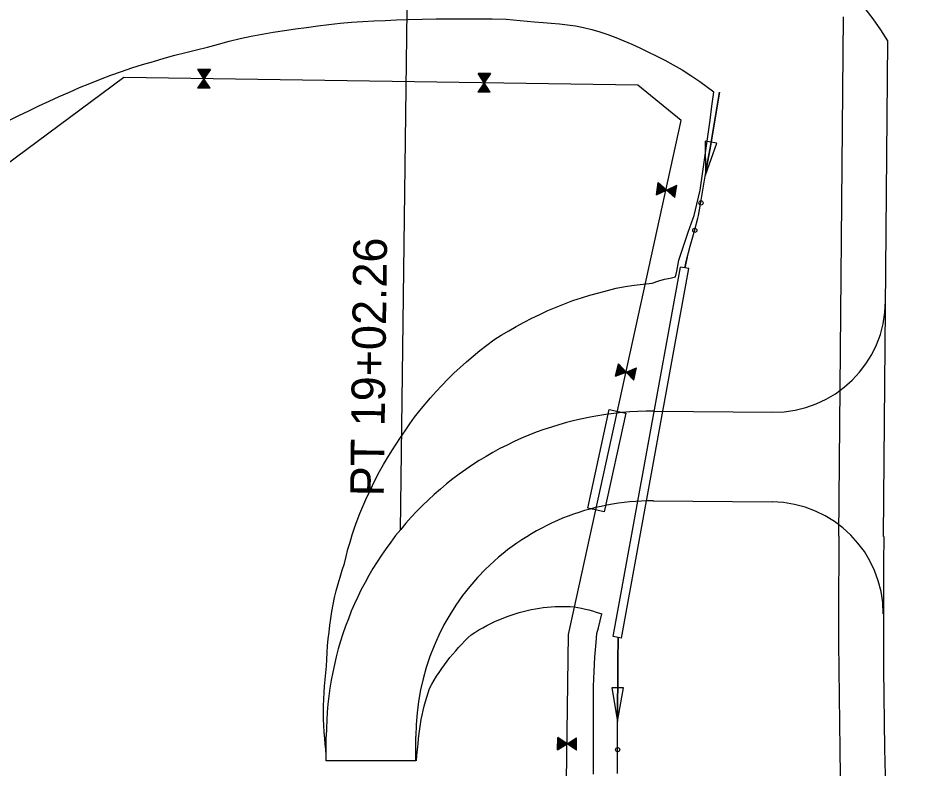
# Model space of a CAD drawing. Extents: x 1311167 to 1314552, y 2087587 to 2090602.
# Drawn here: x 1313838.8 to 1313997.5, y 2090039.3 to 2090173.1 of the extents above; entities that cross this region are included whole.
import ezdxf

# ---------------------------------------------------------------- set-up
doc = ezdxf.new("R2010")
doc.units = 0
for name, color, linetype in [('MOT_Shoulder_1A', 7, 'Continuous'), ('R_Horz Alg Stationing', 7, 'Continuous'), ('R_Proposed Road', 7, 'Continuous'), ('R_Shld_GR', 7, 'Continuous'), ('S_DITCHLINE', 7, 'Continuous'), ('S_DROP_INLET', 7, 'Continuous'), ('S_EDGE_BITUMINOUS', 7, 'Continuous'), ('S_EDGE_CONCRETE', 7, 'Continuous'), ('S_EDGE_PAVEMENT', 7, 'Continuous'), ('S_PAVEMENT_CROWN', 7, 'Continuous')]:
    doc.layers.add(name, color=color, linetype=linetype)

msp = doc.modelspace()

# ---------------------------------------------------------------- linework, layer by layer
at = {"layer": 'MOT_Shoulder_1A'}
for p, q in [((1313952.36, 2090102.93), (1313973.52, 2090102.75)), ((1313952.22, 2090086.93), (1313973.45, 2090086.75)), ((1313893.86, 2090040.57), (1313893.86, 2090044.93)), ((1313909.86, 2090040.57), (1313909.86, 2090044.93)), ((1313909.86, 2090040.57), (1313893.86, 2090040.57))]:
    msp.add_line(p, q, dxfattribs=at)
for centre, radius, start, end in [((1313973.69, 2090122.75), 20, 269.5, 359.5), ((1313951.86, 2090044.93), 58, 89.5, 180), ((1313951.86, 2090044.93), 42, 89.5, 180), ((1313973.27, 2090066.75), 20, 0.048, 89.5)]:
    msp.add_arc(centre, radius, start, end, dxfattribs=at)
at = {"layer": 'R_Horz Alg Stationing'}
msp.add_arc((1313903.45, 2090013.7), 190.97, 89.1292, 178.95, dxfattribs=at)
at = {"layer": 'R_Proposed Road'}
msp.add_arc((1313906.1, 2090010.65), 201.04, 89.25, 178.95, dxfattribs=at)
msp.add_arc((1313906.1, 2090010.65), 201.04, 89.25, 178.95, dxfattribs=at)
at = {"layer": 'R_Shld_GR'}
msp.add_lwpolyline([(1313908.73, 2090211.67), (1313907.03, 2090081.68)], dxfattribs=at)
at = {"layer": 'S_DITCHLINE'}
for p, q in [((1313963.58, 2090150.78), (1313961.49, 2090151.13)), ((1313961.49, 2090151.13), (1313961.53, 2090145.04)), ((1313961.53, 2090145.04), (1313963.58, 2090150.78)), ((1313946.92, 2090053.57), (1313944.81, 2090053.58)), ((1313944.81, 2090053.58), (1313945.84, 2090047.58)), ((1313946.92, 2090053.57), (1313944.81, 2090053.58)), ((1313944.81, 2090053.58), (1313945.84, 2090047.58)), ((1313945.84, 2090047.58), (1313946.92, 2090053.57)), ((1313945.84, 2090047.58), (1313946.92, 2090053.57))]:
    msp.add_line(p, q, dxfattribs=at)
for points in [[(1313957.84, 2090128.51), (1313958.13, 2090129.88), (1313958.81, 2090132.38), (1313959.49, 2090134.87), (1313960.17, 2090137.37), (1313960.31, 2090137.86), (1313960.65, 2090139.86), (1313961.08, 2090142.36), (1313961.5, 2090144.85), (1313961.92, 2090147.35), (1313962.35, 2090149.85), (1313962.77, 2090152.34), (1313963.19, 2090154.84), (1313963.6, 2090157.34), (1313964.02, 2090159.83)], [(1313964.02, 2090159.83), (1313963.6, 2090157.34), (1313963.19, 2090154.84), (1313962.77, 2090152.34), (1313962.35, 2090149.85), (1313961.92, 2090147.35), (1313961.53, 2090145.04)], [(1313958.26, 2090130.38), (1313958.13, 2090129.88), (1313957.84, 2090128.51)], [(1313958.27, 2090130.42), (1313958.26, 2090130.38)], [(1313945.82, 2090038.28), (1313945.82, 2090040.89), (1313945.83, 2090043.49), (1313945.83, 2090046.1), (1313945.84, 2090048.7), (1313945.85, 2090051.3), (1313945.87, 2090053.91), (1313945.89, 2090056.51), (1313945.91, 2090059.12), (1313945.93, 2090061.72), (1313945.94, 2090062.58)], [(1313945.94, 2090062.58), (1313945.93, 2090061.72), (1313945.91, 2090059.12), (1313945.89, 2090056.51), (1313945.87, 2090053.91), (1313945.85, 2090051.3), (1313945.84, 2090048.7), (1313945.84, 2090047.58)], [(1313945.94, 2090062.58), (1313945.93, 2090061.72), (1313945.91, 2090059.12), (1313945.89, 2090056.51), (1313945.87, 2090053.91), (1313945.85, 2090051.3), (1313945.84, 2090048.7), (1313945.84, 2090047.58)]]:
    msp.add_lwpolyline(points, dxfattribs=at)
for centre in [(1313960.73, 2090140.1), (1313959.62, 2090135.21), (1313945.86, 2090042.57), (1313945.86, 2090042.57)]:
    msp.add_circle(centre, 0.375, dxfattribs=at)
at = {"layer": 'S_DROP_INLET'}
for p, q in [((1313872.03, 2090162.25), (1313870.94, 2090163.94)), ((1313872.05, 2090162.29), (1313870.99, 2090163.94)), ((1313872.11, 2090162.41), (1313871.12, 2090163.93)), ((1313872.19, 2090162.49), (1313871.26, 2090163.93)), ((1313872.25, 2090162.6), (1313871.39, 2090163.93)), ((1313872.32, 2090162.69), (1313871.52, 2090163.93)), ((1313872.38, 2090162.81), (1313871.66, 2090163.93)), ((1313872.46, 2090162.89), (1313871.79, 2090163.92)), ((1313872.51, 2090163.01), (1313871.92, 2090163.92)), ((1313873.17, 2090163.9), (1313872.03, 2090162.25)), ((1313872.59, 2090163.1), (1313872.06, 2090163.92)), ((1313872.64, 2090163.22), (1313872.23, 2090163.86)), ((1313872.73, 2090163.29), (1313872.32, 2090163.92)), ((1313872.8, 2090163.38), (1313872.46, 2090163.91)), ((1313872.87, 2090163.48), (1313872.59, 2090163.91)), ((1313872.93, 2090163.59), (1313872.72, 2090163.91)), ((1313873, 2090163.68), (1313872.86, 2090163.91)), ((1313873.07, 2090163.79), (1313872.99, 2090163.91)), ((1313873.14, 2090163.88), (1313873.13, 2090163.9)), ((1313872.03, 2090162.25), (1313870.9, 2090160.6)), ((1313872.05, 2090162.21), (1313870.94, 2090160.6)), ((1313872.1, 2090162.09), (1313871.07, 2090160.6)), ((1313873.12, 2090160.57), (1313872.03, 2090162.25)), ((1313922.03, 2090161.53), (1313920.94, 2090163.21)), ((1313922.04, 2090161.57), (1313920.98, 2090163.21)), ((1313922.1, 2090161.68), (1313921.12, 2090163.21)), ((1313922.18, 2090161.77), (1313921.25, 2090163.2)), ((1313922.24, 2090161.87), (1313921.38, 2090163.2)), ((1313922.32, 2090161.96), (1313921.52, 2090163.2)), ((1313922.37, 2090162.08), (1313921.65, 2090163.2)), ((1313922.45, 2090162.16), (1313921.78, 2090163.2)), ((1313922.51, 2090162.28), (1313921.92, 2090163.19)), ((1313923.16, 2090163.18), (1313922.03, 2090161.53)), ((1313922.58, 2090162.37), (1313922.05, 2090163.19)), ((1313922.64, 2090162.49), (1313922.23, 2090163.13)), ((1313922.73, 2090162.56), (1313922.32, 2090163.19)), ((1313922.8, 2090162.65), (1313922.45, 2090163.19)), ((1313922.86, 2090162.76), (1313922.59, 2090163.18)), ((1313922.93, 2090162.86), (1313922.72, 2090163.18)), ((1313923, 2090162.95), (1313922.85, 2090163.18)), ((1313923.06, 2090163.06), (1313922.99, 2090163.18)), ((1313923.14, 2090163.15), (1313923.12, 2090163.18)), ((1313872.18, 2090162.01), (1313871.21, 2090160.6)), ((1313872.24, 2090161.9), (1313871.34, 2090160.6)), ((1313872.31, 2090161.81), (1313871.47, 2090160.59)), ((1313872.36, 2090161.69), (1313871.61, 2090160.59)), ((1313872.44, 2090161.61), (1313871.74, 2090160.59)), ((1313872.49, 2090161.49), (1313871.87, 2090160.59)), ((1313872.56, 2090161.39), (1313872.01, 2090160.59)), ((1313872.61, 2090161.27), (1313872.18, 2090160.65)), ((1313872.7, 2090161.2), (1313872.28, 2090160.58)), ((1313872.77, 2090161.11), (1313872.41, 2090160.58)), ((1313872.83, 2090161), (1313872.54, 2090160.58)), ((1313872.89, 2090160.89), (1313872.68, 2090160.58)), ((1313872.96, 2090160.8), (1313872.81, 2090160.58)), ((1313873.02, 2090160.69), (1313872.94, 2090160.57)), ((1313873.09, 2090160.6), (1313873.08, 2090160.57)), ((1313922.03, 2090161.53), (1313920.89, 2090159.88)), ((1313922.04, 2090161.48), (1313920.94, 2090159.88)), ((1313922.1, 2090161.37), (1313921.07, 2090159.87)), ((1313922.17, 2090161.28), (1313921.2, 2090159.87)), ((1313922.23, 2090161.17), (1313921.34, 2090159.87)), ((1313922.3, 2090161.08), (1313921.47, 2090159.87)), ((1313922.36, 2090160.96), (1313921.6, 2090159.87)), ((1313922.43, 2090160.88), (1313921.74, 2090159.86)), ((1313922.49, 2090160.76), (1313921.87, 2090159.86)), ((1313922.56, 2090160.67), (1313922, 2090159.86)), ((1313923.11, 2090159.84), (1313922.03, 2090161.53)), ((1313922.61, 2090160.54), (1313922.18, 2090159.92)), ((1313957.22, 2090154.8), (1313949.47, 2090161.13)), ((1313922.7, 2090160.47), (1313922.27, 2090159.86)), ((1313922.77, 2090160.38), (1313922.4, 2090159.85)), ((1313922.83, 2090160.27), (1313922.54, 2090159.85)), ((1313922.89, 2090160.16), (1313922.67, 2090159.85)), ((1313922.96, 2090160.07), (1313922.8, 2090159.85)), ((1313923.02, 2090159.96), (1313922.94, 2090159.85)), ((1313923.09, 2090159.87), (1313923.07, 2090159.84)), ((1313954.12, 2090142.18), (1313953.03, 2090143.17)), ((1313954.22, 2090142.23), (1313953.05, 2090143.3)), ((1313954.33, 2090142.28), (1313953.07, 2090143.43)), ((1313954.43, 2090142.34), (1313953.09, 2090143.56)), ((1313954.6, 2090142.39), (1313953.11, 2090143.74)), ((1313954.55, 2090142.38), (1313953.11, 2090143.69)), ((1313954.6, 2090142.39), (1313956.41, 2090143.24)), ((1313954.63, 2090142.37), (1313956.4, 2090143.2)), ((1313954.74, 2090142.3), (1313956.38, 2090143.07)), ((1313952.78, 2090141.54), (1313954.6, 2090142.39)), ((1313952.81, 2090141.56), (1313952.79, 2090141.58)), ((1313952.91, 2090141.62), (1313952.81, 2090141.71)), ((1313953.03, 2090141.66), (1313952.83, 2090141.85)), ((1313953.13, 2090141.72), (1313952.85, 2090141.98)), ((1313953.25, 2090141.77), (1313952.87, 2090142.11)), ((1313953.36, 2090141.81), (1313952.89, 2090142.24)), ((1313953.46, 2090141.87), (1313952.91, 2090142.37)), ((1313953.67, 2090141.98), (1313952.95, 2090142.64)), ((1313953.77, 2090142.04), (1313952.97, 2090142.77)), ((1313953.54, 2090141.95), (1313952.98, 2090142.46)), ((1313953.9, 2090142.07), (1313952.99, 2090142.9)), ((1313953.99, 2090142.14), (1313953.01, 2090143.03)), ((1313956.08, 2090141.05), (1313954.6, 2090142.39)), ((1313954.81, 2090142.21), (1313956.36, 2090142.94)), ((1313954.91, 2090142.13), (1313956.34, 2090142.8)), ((1313954.99, 2090142.05), (1313956.32, 2090142.67)), ((1313955.1, 2090141.97), (1313956.3, 2090142.54)), ((1313955.17, 2090141.88), (1313956.28, 2090142.41)), ((1313955.28, 2090141.81), (1313956.26, 2090142.28)), ((1313955.36, 2090141.73), (1313956.24, 2090142.14)), ((1313955.47, 2090141.66), (1313956.16, 2090141.98)), ((1313955.52, 2090141.56), (1313956.2, 2090141.88)), ((1313955.61, 2090141.48), (1313956.18, 2090141.75)), ((1313955.7, 2090141.4), (1313956.16, 2090141.61)), ((1313955.8, 2090141.32), (1313956.14, 2090141.48)), ((1313955.88, 2090141.24), (1313956.12, 2090141.35)), ((1313955.98, 2090141.16), (1313956.1, 2090141.22)), ((1313956.06, 2090141.07), (1313956.08, 2090141.09)), ((1313947.33, 2090109.93), (1313945.97, 2090111.33)), ((1313947.37, 2090109.93), (1313945.98, 2090111.38)), ((1313945.5, 2090109.21), (1313947.37, 2090109.93)), ((1313945.98, 2090109.4), (1313945.63, 2090109.77)), ((1313946.1, 2090109.44), (1313945.66, 2090109.9)), ((1313946.21, 2090109.49), (1313945.69, 2090110.03)), ((1313946.42, 2090109.58), (1313945.74, 2090110.29)), ((1313946.29, 2090109.56), (1313945.76, 2090110.11)), ((1313946.53, 2090109.64), (1313945.77, 2090110.42)), ((1313946.65, 2090109.66), (1313945.8, 2090110.55)), ((1313946.75, 2090109.72), (1313945.83, 2090110.68)), ((1313946.88, 2090109.75), (1313945.86, 2090110.81)), ((1313946.98, 2090109.8), (1313945.89, 2090110.94)), ((1313947.1, 2090109.84), (1313945.91, 2090111.07)), ((1313947.2, 2090109.9), (1313945.94, 2090111.2)), ((1313947.37, 2090109.93), (1313949.24, 2090110.66)), ((1313948.76, 2090108.49), (1313947.37, 2090109.93)), ((1313947.41, 2090109.91), (1313949.23, 2090110.62)), ((1313947.51, 2090109.83), (1313949.2, 2090110.49)), ((1313947.57, 2090109.74), (1313949.17, 2090110.36)), ((1313947.67, 2090109.65), (1313949.14, 2090110.23)), ((1313947.74, 2090109.56), (1313949.11, 2090110.1)), ((1313947.84, 2090109.48), (1313949.08, 2090109.97)), ((1313947.91, 2090109.39), (1313949.06, 2090109.84)), ((1313948.01, 2090109.31), (1313949.03, 2090109.71)), ((1313945.53, 2090109.23), (1313945.51, 2090109.25)), ((1313945.64, 2090109.28), (1313945.54, 2090109.38)), ((1313945.76, 2090109.31), (1313945.57, 2090109.51)), ((1313945.86, 2090109.36), (1313945.6, 2090109.64)), ((1313948.09, 2090109.22), (1313949, 2090109.58)), ((1313948.19, 2090109.14), (1313948.9, 2090109.42)), ((1313948.24, 2090109.04), (1313948.94, 2090109.31)), ((1313948.32, 2090108.95), (1313948.91, 2090109.18)), ((1313948.41, 2090108.87), (1313948.88, 2090109.05)), ((1313948.5, 2090108.79), (1313948.86, 2090108.92)), ((1313948.58, 2090108.69), (1313948.83, 2090108.79)), ((1313948.67, 2090108.61), (1313948.8, 2090108.66)), ((1313948.74, 2090108.52), (1313948.77, 2090108.53)), ((1313936.8, 2090043.6), (1313935.18, 2090044.7)), ((1313936.84, 2090043.61), (1313935.19, 2090044.75)), ((1313936.84, 2090043.61), (1313938.52, 2090044.7)), ((1313936.88, 2090043.59), (1313938.52, 2090044.66)), ((1313935.15, 2090042.52), (1313936.84, 2090043.61)), ((1313935.69, 2090042.87), (1313935.16, 2090043.23)), ((1313935.58, 2090042.81), (1313935.16, 2090043.1)), ((1313936.19, 2090043.2), (1313935.17, 2090043.9)), ((1313936.07, 2090043.15), (1313935.17, 2090043.77)), ((1313935.98, 2090043.08), (1313935.17, 2090043.63)), ((1313935.79, 2090042.94), (1313935.17, 2090043.37)), ((1313936.68, 2090043.54), (1313935.18, 2090044.57)), ((1313936.59, 2090043.46), (1313935.18, 2090044.43)), ((1313936.48, 2090043.4), (1313935.18, 2090044.3)), ((1313936.39, 2090043.33), (1313935.18, 2090044.17)), ((1313936.27, 2090043.28), (1313935.18, 2090044.03)), ((1313935.86, 2090043.03), (1313935.23, 2090043.46)), ((1313938.49, 2090042.48), (1313936.84, 2090043.61)), ((1313936.99, 2090043.54), (1313938.52, 2090044.52)), ((1313937.08, 2090043.46), (1313938.51, 2090044.39)), ((1313937.18, 2090043.39), (1313938.51, 2090044.25)), ((1313937.27, 2090043.32), (1313938.51, 2090044.12)), ((1313937.39, 2090043.27), (1313938.51, 2090043.99)), ((1313937.47, 2090043.19), (1313938.51, 2090043.85)), ((1313937.59, 2090043.13), (1313938.51, 2090043.72)), ((1313937.68, 2090043.06), (1313938.5, 2090043.59)), ((1313937.8, 2090043), (1313938.44, 2090043.41)), ((1313937.87, 2090042.91), (1313938.5, 2090043.32)), ((1313937.96, 2090042.84), (1313938.5, 2090043.19)), ((1313938.07, 2090042.78), (1313938.5, 2090043.05)), ((1313935.47, 2090042.75), (1313935.16, 2090042.97)), ((1313935.38, 2090042.68), (1313935.16, 2090042.83)), ((1313935.27, 2090042.62), (1313935.16, 2090042.7)), ((1313935.18, 2090042.55), (1313935.16, 2090042.56)), ((1313938.17, 2090042.71), (1313938.49, 2090042.92)), ((1313938.27, 2090042.64), (1313938.49, 2090042.79)), ((1313938.37, 2090042.58), (1313938.49, 2090042.65)), ((1313938.46, 2090042.5), (1313938.49, 2090042.52))]:
    msp.add_line(p, q, dxfattribs=at)
for points in [[(1313873.17, 2090163.9), (1313870.94, 2090163.94)], [(1313949.47, 2090161.13), (1313857.75, 2090162.46), (1313774.8, 2090101), (1313754.78, 2090060.06), (1313753.38, 2090042.36)], [(1313923.16, 2090163.18), (1313920.94, 2090163.21)], [(1313873.12, 2090160.57), (1313870.9, 2090160.6)], [(1313949.47, 2090161.13), (1313949.47, 2090161.13)], [(1313923.11, 2090159.84), (1313920.89, 2090159.88)], [(1313938.24, 2089808.01), (1313935.42, 2089941.12), (1313937.11, 2090063.1), (1313957.22, 2090154.8)], [(1313952.78, 2090141.54), (1313953.11, 2090143.74)], [(1313956.08, 2090141.05), (1313956.41, 2090143.24)], [(1313945.5, 2090109.21), (1313945.98, 2090111.38)], [(1313948.76, 2090108.49), (1313949.24, 2090110.66)], [(1313935.15, 2090042.52), (1313935.19, 2090044.75)], [(1313938.49, 2090042.48), (1313938.52, 2090044.7)]]:
    msp.add_lwpolyline(points, dxfattribs=at)
msp.add_lwpolyline([(1313940.52, 2090085.66), (1313944.37, 2090103.24), (1313947.3, 2090102.6), (1313943.45, 2090085.01)], close=True, dxfattribs=at)
at = {"layer": 'S_EDGE_BITUMINOUS'}
for p, q in [((1313945.06, 2090062.74), (1313957.1, 2090128.65)), ((1313946.53, 2090062.47), (1313958.57, 2090128.38)), ((1313958.57, 2090128.38), (1313957.1, 2090128.65)), ((1313946.53, 2090062.47), (1313945.06, 2090062.74))]:
    msp.add_line(p, q, dxfattribs=at)
at = {"layer": 'S_EDGE_CONCRETE'}
for points in [[(1313837.21, 2090154.8), (1313838.99, 2090155.67), (1313840.78, 2090156.55), (1313842.57, 2090157.41), (1313844.37, 2090158.25), (1313846.19, 2090159.08), (1313848.01, 2090159.88), (1313849.84, 2090160.67), (1313851.68, 2090161.43), (1313853.53, 2090162.18), (1313855.39, 2090162.9), (1313857.28, 2090163.57), (1313859.17, 2090164.19), (1313861.08, 2090164.78), (1313862.99, 2090165.36), (1313864.91, 2090165.91), (1313866.84, 2090166.45), (1313868.77, 2090166.96), (1313870.71, 2090167.44), (1313872.65, 2090167.91), (1313874.59, 2090168.43), (1313876.53, 2090168.95), (1313878.47, 2090169.44), (1313880.44, 2090169.85), (1313882.41, 2090170.21), (1313884.39, 2090170.55), (1313886.37, 2090170.86), (1313888.36, 2090171.14), (1313890.35, 2090171.4), (1313892.35, 2090171.67), (1313894.34, 2090171.93), (1313896.34, 2090172.15), (1313898.35, 2090172.33), (1313900.36, 2090172.47), (1313902.37, 2090172.58), (1313904.38, 2090172.66), (1313906.4, 2090172.74), (1313908.46, 2090172.82), (1313910.96, 2090172.88), (1313913.46, 2090172.94), (1313915.96, 2090172.95), (1313918.46, 2090172.96), (1313920.96, 2090172.96), (1313923.46, 2090172.92), (1313925.96, 2090172.88), (1313928.46, 2090172.65), (1313930.96, 2090172.43), (1313932.56, 2090172.29), (1313934, 2090172.14), (1313935.45, 2090172.03), (1313936.89, 2090171.88), (1313938.34, 2090171.67), (1313939.79, 2090171.41), (1313941.23, 2090171.05), (1313942.66, 2090170.61), (1313944.09, 2090170.13), (1313945.51, 2090169.6), (1313946.94, 2090169.02), (1313948.37, 2090168.41), (1313949.82, 2090167.76), (1313951.27, 2090167.06), (1313952.75, 2090166.33), (1313954.26, 2090165.56), (1313955.79, 2090164.73), (1313957.35, 2090163.82), (1313958.93, 2090162.83), (1313960.54, 2090161.74), (1313963.02, 2090159.94)], [(1313956.21, 2090126.9), (1313956.41, 2090127.9), (1313956.78, 2090129.89), (1313957.61, 2090132.39), (1313958.47, 2090134.88), (1313959.34, 2090137.37), (1313959.51, 2090137.87), (1313959.99, 2090139.87), (1313960.57, 2090142.36), (1313960.93, 2090144.86), (1313961.28, 2090147.36), (1313961.64, 2090149.85), (1313961.99, 2090152.35), (1313962.34, 2090154.85), (1313962.69, 2090157.34), (1313963.04, 2090159.84)], [(1313893.85, 2090041.57), (1313893.76, 2090042.57), (1313893.67, 2090043.57), (1313893.58, 2090044.57), (1313893.49, 2090045.68), (1313893.43, 2090046.85), (1313893.38, 2090048.02), (1313893.36, 2090049.19), (1313893.37, 2090050.37), (1313893.4, 2090051.55), (1313893.45, 2090052.73), (1313893.53, 2090053.91), (1313893.63, 2090055.09), (1313893.75, 2090056.27), (1313893.9, 2090057.45), (1313893.94, 2090058.66), (1313894, 2090059.87), (1313894.09, 2090061.09), (1313894.21, 2090062.31), (1313894.35, 2090063.53), (1313894.5, 2090064.75), (1313894.67, 2090065.99), (1313894.86, 2090067.22), (1313895.08, 2090068.45), (1313895.34, 2090069.68), (1313895.64, 2090070.9), (1313895.96, 2090072.12), (1313896.31, 2090073.34), (1313896.68, 2090074.56), (1313897.08, 2090075.77), (1313897.39, 2090077.05), (1313897.73, 2090078.32), (1313898.09, 2090079.6), (1313898.49, 2090080.87), (1313898.92, 2090082.15), (1313899.37, 2090083.42), (1313899.86, 2090084.69), (1313900.37, 2090085.95), (1313900.91, 2090087.21), (1313901.49, 2090088.46), (1313902.09, 2090089.71), (1313902.72, 2090090.96), (1313903.38, 2090092.19), (1313904.08, 2090093.42), (1313904.8, 2090094.64), (1313905.55, 2090095.85), (1313906.33, 2090097.05), (1313907.12, 2090098.25), (1313907.92, 2090099.47), (1313908.76, 2090100.68), (1313909.62, 2090101.88), (1313910.54, 2090103.04), (1313911.48, 2090104.19), (1313912.45, 2090105.33), (1313913.45, 2090106.45), (1313914.48, 2090107.55), (1313915.54, 2090108.64), (1313916.63, 2090109.7), (1313917.75, 2090110.74), (1313918.9, 2090111.77), (1313920.08, 2090112.77), (1313921.28, 2090113.76), (1313922.5, 2090114.73), (1313923.76, 2090115.67), (1313925.06, 2090116.53), (1313926.41, 2090117.3), (1313927.77, 2090118.07), (1313929.16, 2090118.81), (1313930.56, 2090119.53), (1313931.98, 2090120.22), (1313933.42, 2090120.88), (1313934.88, 2090121.51), (1313936.36, 2090122.12), (1313937.86, 2090122.69), (1313939.38, 2090123.18), (1313940.92, 2090123.63), (1313942.47, 2090124.05), (1313944.03, 2090124.49), (1313945.6, 2090124.9), (1313947.19, 2090125.22), (1313948.79, 2090125.43), (1313950.4, 2090125.61), (1313952.01, 2090125.77), (1313953.22, 2090126.18), (1313954.23, 2090126.49), (1313955.23, 2090126.68), (1313956.21, 2090126.9)], [(1313909.95, 2090040.57), (1313910.04, 2090041.57), (1313910.13, 2090042.57), (1313910.23, 2090043.57), (1313910.32, 2090044.57), (1313910.42, 2090045.46), (1313910.53, 2090046.29), (1313910.66, 2090047.11), (1313910.81, 2090047.92), (1313910.97, 2090048.74), (1313911.15, 2090049.54), (1313911.35, 2090050.34), (1313911.56, 2090051.14), (1313911.78, 2090051.92), (1313912.03, 2090052.71), (1313912.28, 2090053.48), (1313912.69, 2090054.22), (1313913.12, 2090054.94), (1313913.55, 2090055.65), (1313914, 2090056.34), (1313914.46, 2090057.02), (1313914.94, 2090057.69), (1313915.42, 2090058.34), (1313915.92, 2090058.98), (1313916.43, 2090059.61), (1313916.95, 2090060.22), (1313917.48, 2090060.81), (1313918.02, 2090061.39), (1313918.57, 2090061.96), (1313919.12, 2090062.51), (1313919.69, 2090063.04), (1313920.38, 2090063.49), (1313921.08, 2090063.91), (1313921.8, 2090064.32), (1313922.51, 2090064.7), (1313923.23, 2090065.06), (1313923.95, 2090065.4), (1313924.67, 2090065.72), (1313925.4, 2090066.01), (1313926.12, 2090066.29), (1313926.84, 2090066.55), (1313927.57, 2090066.79), (1313928.29, 2090067.01), (1313929.01, 2090067.2), (1313929.73, 2090067.38), (1313930.45, 2090067.54), (1313931.17, 2090067.68), (1313931.88, 2090067.8), (1313932.59, 2090067.9), (1313933.29, 2090067.98), (1313933.99, 2090068.05), (1313934.68, 2090068.09), (1313935.37, 2090068.12), (1313936.05, 2090068.13), (1313936.73, 2090068.12), (1313937.39, 2090068.1), (1313938.07, 2090068.03), (1313938.75, 2090067.92), (1313939.43, 2090067.79), (1313940.09, 2090067.65), (1313940.74, 2090067.48), (1313941.37, 2090067.31), (1313942, 2090067.12), (1313943.05, 2090066.77)], [(1313941.57, 2090038.2), (1313941.57, 2090040.81), (1313941.56, 2090043.42), (1313941.54, 2090046.03), (1313941.53, 2090048.64), (1313941.52, 2090051.26), (1313941.52, 2090053.87), (1313941.64, 2090056.48), (1313941.81, 2090059.09), (1313942.01, 2090061.7), (1313942.13, 2090063.27), (1313942.41, 2090064.32), (1313943.05, 2090066.77)]]:
    msp.add_lwpolyline(points, dxfattribs=at)
at = {"layer": 'S_EDGE_PAVEMENT'}
msp.add_line((1313985.33, 2090080.65), (1313986.14, 2090173.29), dxfattribs=at)
for centre, radius, start, end in [((1313906.1, 2090010.65), 214.54, 96.0197, 139.7699), ((1313906.1, 2090010.65), 189.54, 89.25, 139.7699), ((1315437.67, 2090067.97), 1452.39, 179.5, 185.5)]:
    msp.add_arc(centre, radius, start, end, dxfattribs=at)
at = {"layer": 'S_PAVEMENT_CROWN'}
msp.add_line((1313993.33, 2090080.58), (1313994.1, 2090169.02), dxfattribs=at)
for centre, radius, start, end in [((1313906.1, 2090010.65), 208.54, 96.0544, 139.7699), ((1313906.1, 2090010.65), 193.54, 89.25, 139.7699), ((1313930.75, 2090128.87), 75, 32.3599, 89.25), ((1315437.67, 2090067.97), 1444.39, 179.5, 185.5)]:
    msp.add_arc(centre, radius, start, end, dxfattribs=at)

# ---------------------------------------------------------------- texts
at = {"layer": 'R_Shld_GR'}
msp.add_text('PT 19+02.26', height=6, rotation=89.25, dxfattribs=at).set_placement((1313904.11, 2090087.72))

doc.saveas('drawing.dxf')
